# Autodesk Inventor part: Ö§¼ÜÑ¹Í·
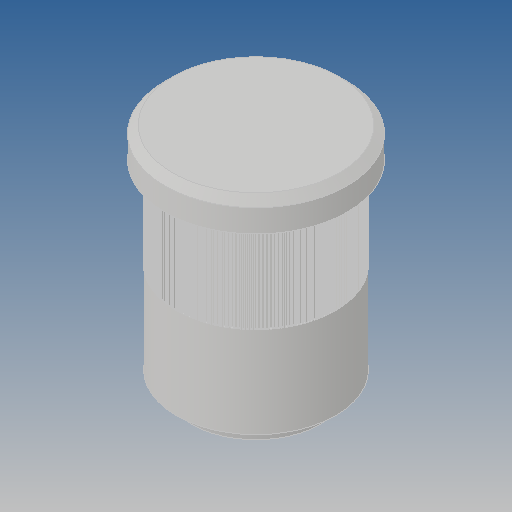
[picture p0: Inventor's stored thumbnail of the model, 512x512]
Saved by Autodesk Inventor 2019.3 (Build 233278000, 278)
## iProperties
Created: 2017-12
Part Number: Ö§¼ÜÑ¹Í·
Material: Ogólny
Document SubType Name: Modeling
Designer: Admin
Density: 1 g/cm^3
Appearance: Domyślna
Author: Admin
Revision Number: ÈÎºÎ
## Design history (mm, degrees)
feature "ÕóÁÐ(Ô²ÖÜ)2"
node "Bryła1"
